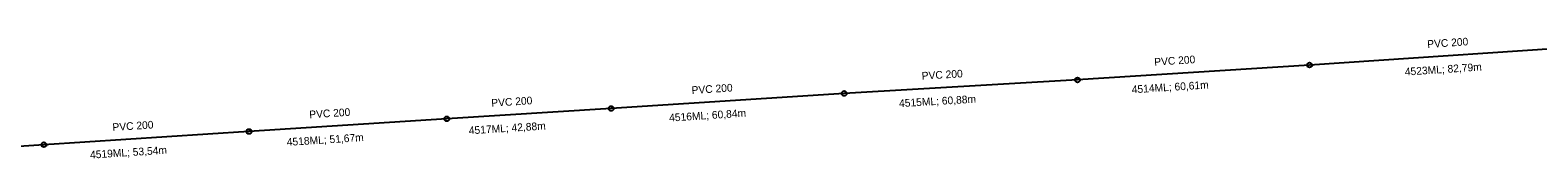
# Model space of a CAD drawing. Extents: x -867696 to -865033, y -1042522 to -1039817.
# Drawn here: x -865818.6 to -865425.8, y -1040835.2 to -1040803.8 of the extents above; entities that cross this region are included whole.
import ezdxf

# ---------------------------------------------------------------- set-up
doc = ezdxf.new("R2010")
doc.units = 0
for name, color, linetype in [('KN - popis material', 7, 'Continuous'), ('KN - popis usek delka', 7, 'Continuous'), ('KN - sachta komora', 7, 'Continuous'), ('KN - splaskova', 7, 'Continuous'), ('Level 1', 7, 'Continuous')]:
    doc.layers.add(name, color=color, linetype=linetype)

# ---------------------------------------------------------------- blocks, each defined once
blk = doc.blocks.new('100.M')
at = {"layer": 'Level 1'}
blk.add_circle((0, 0), 1.27, dxfattribs=at)

msp = doc.modelspace()

# ---------------------------------------------------------------- linework, layer by layer
at = {"layer": 'KN - splaskova'}
for points in [[(-865402.644, -1040805.416), (-865485.246, -1040810.93)], [(-865485.246, -1040810.93), (-865545.729, -1040814.793)], [(-865545.729, -1040814.793), (-865606.504, -1040818.313)], [(-865606.504, -1040818.313), (-865667.222, -1040822.228)], [(-865667.222, -1040822.228), (-865710.021, -1040824.932)], [(-865710.021, -1040824.932), (-865761.582, -1040828.218)], [(-865761.582, -1040828.218), (-865815.012, -1040831.68)], [(-865815.012, -1040831.68), (-865863.216, -1040834.935)]]:
    msp.add_lwpolyline(points, dxfattribs=at)

# ---------------------------------------------------------------- block references
at = {"layer": 'KN - sachta komora', "xscale": 0.5000000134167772, "yscale": 0.5000000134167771, "rotation": -176.00000028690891}
for p in [(-865485.246, -1040810.93), (-865545.729, -1040814.793), (-865606.504, -1040818.313), (-865667.222, -1040822.228), (-865710.021, -1040824.932), (-865761.582, -1040828.218), (-865815.012, -1040831.68)]:
    msp.add_blockref('100.M', p, dxfattribs=at)

# ---------------------------------------------------------------- texts
at = {"layer": 'KN - popis material'}
for rotation, p in [(3.82, (-865454.538, -1040806.475)), (3.65, (-865525.668, -1040811.106)), (3.31, (-865586.259, -1040814.735)), (3.69, (-865646.205, -1040818.468)), (3.65, (-865745.821, -1040824.809)), (3.62, (-865698.392, -1040821.793)), (3.71, (-865797.092, -1040828.114))]:
    msp.add_text('PVC 200', height=2, rotation=rotation, dxfattribs=at).set_placement(p)
at = {"layer": 'KN - popis usek delka'}
for s, rotation, p in [('4523ML; 82,79m', 3.82, (-865460.371, -1040813.679)), ('4515ML; 60,88m', 3.31, (-865592.154, -1040821.888)), ('4514ML; 60,61m', 3.65, (-865531.522, -1040818.293)), ('4516ML; 60,84m', 3.69, (-865652.053, -1040825.659)), ('4517ML; 42,88m', 3.62, (-865704.25, -1040828.978)), ('4518ML; 51,67m', 3.65, (-865751.675, -1040831.996)), ('4519ML; 53,54m', 3.71, (-865802.938, -1040835.307))]:
    msp.add_text(s, height=1.99999, rotation=rotation, dxfattribs=at).set_placement(p)

doc.saveas('drawing.dxf')
